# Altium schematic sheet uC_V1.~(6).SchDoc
size A4; SheetNumber: 2; SheetTotal: 7
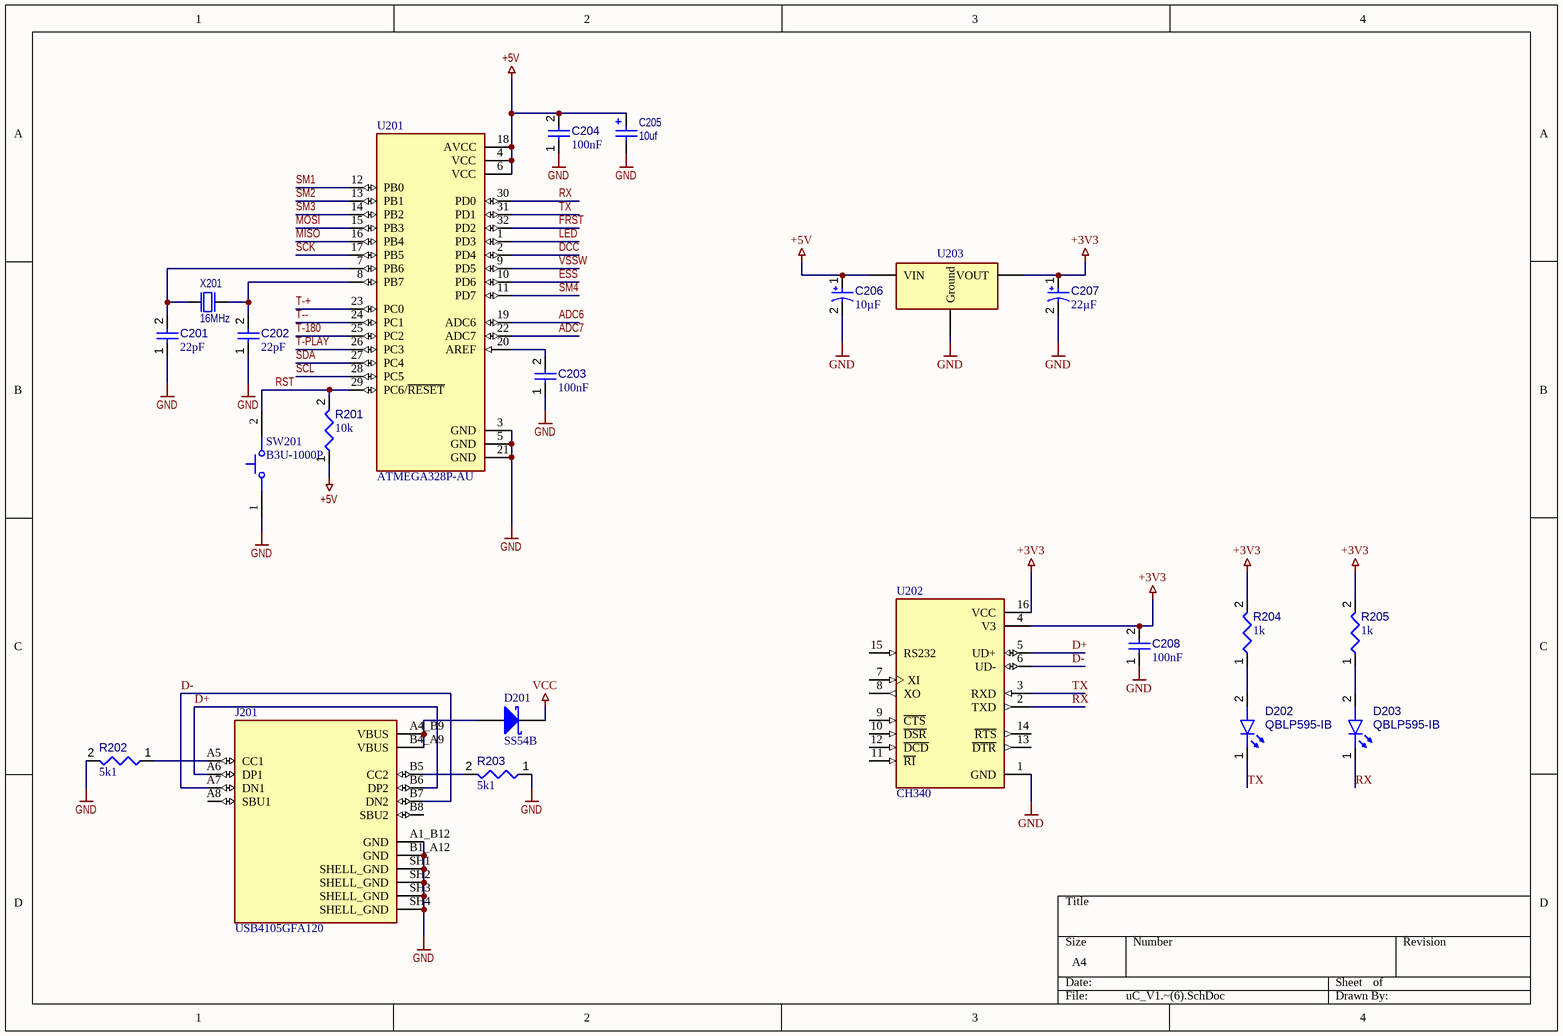
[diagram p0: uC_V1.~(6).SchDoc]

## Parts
C201  22pF  [CAPC1608X90X40NL10T20]
C202  22pF  [CAPC1608X90X40NL10T20]
C203  100nF  [CAPC1608X90X40NL10T20]
C204  100nF  [CAPC1608X90X40NL10T20]
C205  10uf  [C_SMD_C-TYP]
C206  value 10µF  [CAPMP3217X18-T_V]  (hidden comment: TAJA106K016RNJ)
C207  value 22µF  [VISH-7343-31_M]  (hidden comment: 293D226X9020D2TE3)
C208  value 100nF  [CAPC1608X90X40NL10T20]  (hidden comment: Capacitor 100 nF +/-10% 50 V 0603)
D201  SS54B  [JCET-SMB-2_M]
D202  QBLP595-IB  [QTB-QBLP595_V]
D203  QBLP595-IB  [QTB-QBLP595_V]
J201  USB4105GFA120  [GCT_USB4105GFA120]
R201  10k  [RESC1608X55X25ML10T15]
R202  5k1  [RESC1608X55X25ML10T15]
R203  5k1  [RESC1608X55X25ML10T15]
R204  value 1k  [RESC1608X55X25ML10T15]  (hidden comment: Resistor 1k +/-1% 0603 100 mW)
R205  value 1k  [RESC1608X55X25ML10T15]  (hidden comment: Resistor 1k +/-1% 0603 100 mW)
SW201  B3U-1000P  [OMRON-B3U-1000_V]
U201  ATMEGA328P-AU  [QFP80P900X900X120-32N]
U202  CH340  [SO-16]
U203  #Wert  [U_SMD_AMS1117]  (value not drawn)
X201  16MHz  [X_SMD_XTAL]

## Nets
+3V3: C207.1 C208.2 R204.2 R205.2 U202.4(V3) U202.16(VCC) U203.2(VOUT)
+5V: C204.2 C205.1 C206.1 R201.1 U201.4(VCC) U201.6(VCC) U201.18(AVCC) U203.3(VIN)
GND: C201.1 C202.1 C203.1 C204.1 C205.2 C206.2 C207.2 C208.1 J201.A1_B12(GND) J201.B1_A12(GND) J201.SH1(SHELL_GND) J201.SH2(SHELL_GND) J201.SH3(SHELL_GND) J201.SH4(SHELL_GND) R202.2 R203.1 SW201.1 U201.3(GND) U201.5(GND) U201.21(GND) U202.1(GND) U203.1(Ground)
VCC: D201.2(K)
ADC6: U201.19(ADC6)
ADC7: U201.22(ADC7)
D+: J201.A6(DP1) J201.B6(DP2) U202.5(UD+)
D-: J201.A7(DN1) J201.B7(DN2) U202.6(UD-)
DCC: U201.2(PD4)
ESS: U201.10(PD6)
FRST: U201.32(PD2)
LED: U201.1(PD3)
MISO: U201.16(PB4)
MOSI: U201.15(PB3)
RST: R201.2 SW201.2 U201.29(PC6/~{RESET})
RX: D203.1(K) U201.30(PD0) U202.2(TXD)
SCK: U201.17(PB5)
SCL: U201.28(PC5)
SDA: U201.27(PC4)
SM1: U201.12(PB0)
SM2: U201.13(PB1)
SM3: U201.14(PB2)
SM4: U201.11(PD7)
T-180: U201.25(PC2)
T-+: U201.23(PC0)
T--: U201.24(PC1)
T-PLAY: U201.26(PC3)
TX: D202.1(K) U201.31(PD1) U202.3(RXD)
VSSW: U201.9(PD5)
NetC201_2: C201.2 U201.7(PB6) X201.1
NetC202_2: C202.2 U201.8(PB7) X201.2
NetC203_2: C203.2 U201.20(AREF)
NetD201_1: D201.1(A) J201.A4_B9(VBUS) J201.B4_A9(VBUS)
NetD202_2: D202.2(A) R204.1
NetD203_2: D203.2(A) R205.1
NetJ201_A5: J201.A5(CC1) R202.1
NetJ201_B5: J201.B5(CC2) R203.2

Not connected (* = marked no-connect by the designer): J201 A8(SBU1) B8(SBU2); U202 7(XI) 8(XO) 9(~{CTS}) 10(~{DSR}) 11(~{RI}) 12(~{DCD}) 13(~{DTR}) 14(~{RTS}) 15(RS232)

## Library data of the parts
C201-C204 C208 = CMP-001-00017-6: Chip Capacitor, 100 nF, +/- 10%, 50 V, 0603 (1608 Metric); Voltage Rating: 50V; Capacitor Type: Ceramic
C205 = C_SMD_ELK: SMD Elektrolytkondensator
C206 = CMP-001-00041-7: Standard Tantalum, 10 uF, +/- 10%, 16 V, -55 to 125 degC, 1206 (3216 Metric), RoHS, Tape and Reel; Manufacturer: AVX; Voltage Rating: 16V; ESR: 3Ohm
C207 = CMP-001-00021-7: Solid Tantalum Chip Capacitor, 22 uF, +/- 10%, 20 V, -55 to 125 degC, 2917 (7343 Metric), RoHS, Tape and Reel; Manufacturer: Vishay Semiconductor; Voltage Rating: 20V
D201 = CMP-004-00006-2: Schottky Barrier Rectifier, 40 V, 5 A, -55 to 150 degC, 2-Pin SMD; Manufacturer: JCET
D202 D203 = CMP-007-00042-3: Chip LED 0402, Blue, 0.02 A, 3.1 to 3.7 V, -40 to 80 degC, 2-Pin SMD, RoHS, Tape and Reel
J201 = USB4105GFA120: USB CONN, 2.0 TYPE C, RCPT, 16POS, SMT; USB Connector Type:USB Type C; USB Standard:USB 2.0; Gender:Receptacle; No. of Positions:16Positions; Connector Mounting:Surface Mount, Through Hole Mount; Orientation:Right Angle RoHS Compliant: Yes; MF: Global Connector Technology
R201-R203 = CMP-009-00017-5: Chip Resistor, 10 KOhm, +/- 1%, 01 W, -55 to 155 degC, 0603 (1608 Metric); Voltage Rating: 50V; Power: 100mW
R204 R205 = CMP-009-00014-5: Chip Resistor, 1 KOhm, +/-1%, 0.1 W, -55 to 155 degC, 0603 (1608 Metric); Voltage Rating: 50V; Power: 100mW; Tolerance: 1%
SW201 = CMP-011-00000-2: Tactile Switch, SPST-NO, 0.05 A, 12 V, -25 to 70 degC, 2-Pin SMD, RoHS, Tape and Reel; Manufacturer: Omron Electronic Components; IP Rating: IP40; Current Rating: 50mA; Max Contact Resistance: 100mohm; Operating Force: 153gf; Throw Configuration: SPST; Resistance: 0.1Ohm; Max Voltage Rating (DC): 12V
U201 = ATMEGA328P-AU: MICROCONTROLLER MCU, 8 BIT, ATMEGA, 20MH; MICROCONTROLLER MCU, 8 BIT, ATMEGA, 20MHZ, TQFP-32; Controller Family/Series:ATmega; CPU Speed:20MHz; Program Memory Size:32KB; RAM Memory Size:2KB; No. of Pins:32Pins; MCU Case Style:TQFP; No. of I/O's:23I/O's; P; MF: Microchip Technology; MP: ATMEGA328PAU
U202 = IC_CH340: UART
U203 = U_SMD_AMS1117: Linearwandler; Manufacturer Part Number: AMS1117-3.3; Manufacturer: Advanced Monolithic Systems; Dropout Voltage: 1.1V; Output Type: Fixed; Nominal Supply Current: 5mA; Output Current: 1A; Output Voltage: 3.3V; Max Power Dissipation: 1.2W; Max Supply Voltage: 15V; Number Of Outputs: 1; Standoff Height: 0.64mm; Max Junction Temp: +125°C
X201 = X_SMD_Quarz: Quarz SMD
